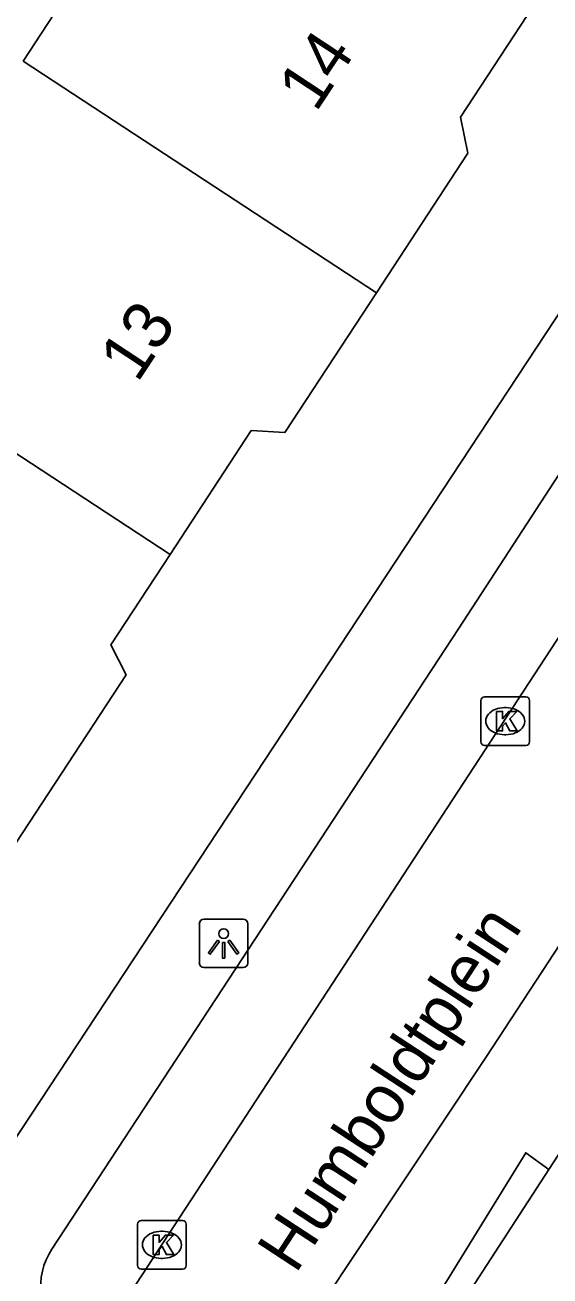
# Model space of a CAD drawing. Extents: x 159280 to 160375, y 384531 to 385872.
# Drawn here: x 160024.02 to 160034.82, y 384678.69 to 384704.43 of the extents above; entities that cross this region are included whole.
import ezdxf

# ---------------------------------------------------------------- set-up
doc = ezdxf.new("R2010")
doc.units = 0
for name, color, linetype in [('IMGEO_Groenvoorziening', 7, 'Continuous'), ('IMGEO_Haag', 7, 'Continuous'), ('IMGEO_Hek', 7, 'Continuous'), ('IMGEO_Kolk', 7, 'Continuous'), ('IMGEO_Lichtpunt', 7, 'Continuous'), ('IMGEO_Openbare_ruimte_label', 7, 'Continuous'), ('IMGEO_Pand', 7, 'Continuous'), ('IMGEO_Pand_nummerreeks', 7, 'Continuous'), ('IMGEO_Rijbaan_lokaal_open', 7, 'Continuous'), ('IMGEO_Voetpad_open', 7, 'Continuous')]:
    doc.layers.add(name, color=color, linetype=linetype)

msp = doc.modelspace()

# ---------------------------------------------------------------- linework, layer by layer
at = {"layer": 'IMGEO_Groenvoorziening'}
msp.add_lwpolyline([(160034.8, 384680.882), (160036.061, 384682.822)], dxfattribs=at)
at = {"layer": 'IMGEO_Haag'}
for points in [[(160048.985, 384693.728), (160048.916, 384693.623), (160048.278, 384692.664), (160051.453, 384690.78), (160040.213, 384673.657), (160033.098, 384678.263), (160034.8, 384680.882)], [(160034.8, 384680.882), (160034.326, 384681.227), (160032.35, 384678.026)]]:
    msp.add_lwpolyline(points, dxfattribs=at)
at = {"layer": 'IMGEO_Hek'}
msp.add_lwpolyline([(160051.453, 384690.78), (160040.213, 384673.657), (160033.098, 384678.263), (160034.8, 384680.882), (160036.061, 384682.822), (160044.27, 384695.449)], dxfattribs=at)
at = {"layer": 'IMGEO_Kolk'}
for p, q in [((160033.479, 384690.608), (160034.331, 384690.608)), ((160033.404, 384689.682), (160033.404, 384690.534)), ((160033.892, 384690.388), (160033.917, 384690.388)), ((160034.405, 384690.534), (160034.405, 384689.682)), ((160033.915, 384689.828), (160033.89, 384689.828)), ((160034.331, 384689.608), (160033.479, 384689.608)), ((160026.339, 384678.907), (160026.339, 384679.759)), ((160026.414, 384679.833), (160027.266, 384679.833)), ((160027.34, 384679.759), (160027.34, 384678.907)), ((160026.827, 384679.613), (160026.852, 384679.613)), ((160026.85, 384679.053), (160026.825, 384679.053)), ((160027.266, 384678.833), (160026.414, 384678.833))]:
    msp.add_line(p, q, dxfattribs=at)
for points in [[(160033.479, 384690.608), (160034.331, 384690.608)], [(160033.404, 384689.682), (160033.404, 384690.534)], [(160033.725, 384690.308), (160033.848, 384690.308), (160033.848, 384690.157), (160033.978, 384690.308), (160034.142, 384690.308), (160033.996, 384690.157), (160034.149, 384689.908), (160033.997, 384689.908), (160033.912, 384690.072), (160033.848, 384690.005), (160033.848, 384689.908), (160033.725, 384689.908), (160033.725, 384690.308)], [(160034.405, 384690.534), (160034.405, 384689.682)], [(160034.331, 384689.608), (160033.479, 384689.608)], [(160026.339, 384678.907), (160026.339, 384679.759)], [(160026.414, 384679.833), (160027.266, 384679.833)], [(160027.34, 384679.759), (160027.34, 384678.907)], [(160026.66, 384679.533), (160026.783, 384679.533), (160026.783, 384679.382), (160026.913, 384679.533), (160027.077, 384679.533), (160026.931, 384679.382), (160027.084, 384679.133), (160026.932, 384679.133), (160026.847, 384679.297), (160026.783, 384679.23), (160026.783, 384679.133), (160026.66, 384679.133), (160026.66, 384679.533)], [(160027.266, 384678.833), (160026.414, 384678.833)]]:
    msp.add_lwpolyline(points, dxfattribs=at)
for centre, start, end in [((160033.481, 384690.532), 91.552, 178.448), ((160033.481, 384690.532), 91.552, 178.448), ((160034.329, 384690.532), 1.552, 88.448), ((160034.329, 384690.532), 1.552, 88.448), ((160033.481, 384689.684), 181.552, 268.448), ((160033.481, 384689.684), 181.552, 268.448), ((160034.329, 384689.684), 271.552, 358.448), ((160034.329, 384689.684), 271.552, 358.448), ((160026.416, 384679.757), 91.552, 178.448), ((160026.416, 384679.757), 91.552, 178.448), ((160027.264, 384679.757), 1.552, 88.448), ((160027.264, 384679.757), 1.552, 88.448), ((160026.416, 384678.909), 181.552, 268.448), ((160026.416, 384678.909), 181.552, 268.448), ((160027.264, 384678.909), 271.552, 358.448), ((160027.264, 384678.909), 271.552, 358.448)]:
    msp.add_arc(centre, 0.0765, start, end, dxfattribs=at)
for centre, major_axis, ratio, start_param, end_param in [((160033.891, 384690.108), (-0.387, 0.002), 0.722429, 4.712389, 7.853982), ((160033.916, 384690.108), (-0.39, 0.002), 0.717154, 1.570796, 4.712389), ((160026.826, 384679.333), (-0.387, 0.002), 0.722429, 4.712389, 7.853982), ((160026.851, 384679.333), (-0.39, 0.002), 0.717154, 1.570796, 4.712389)]:
    msp.add_ellipse(centre, major_axis=major_axis, ratio=ratio, start_param=start_param, end_param=end_param, dxfattribs=at)
at = {"layer": 'IMGEO_Lichtpunt'}
for p, q in [((160027.61, 384685.938), (160027.61, 384685.131)), ((160027.61, 384685.938), (160027.61, 384685.131)), ((160028.512, 384686.033), (160027.704, 384686.033)), ((160028.512, 384686.033), (160027.704, 384686.033)), ((160028.606, 384685.131), (160028.606, 384685.938)), ((160028.606, 384685.131), (160028.606, 384685.938)), ((160027.704, 384685.037), (160028.512, 384685.037)), ((160027.704, 384685.037), (160028.512, 384685.037))]:
    msp.add_line(p, q, dxfattribs=at)
for points in [[(160027.984, 384685.602), (160028.023, 384685.574), (160027.835, 384685.312), (160027.797, 384685.339), (160027.984, 384685.602)], [(160028.086, 384685.554), (160028.133, 384685.554), (160028.133, 384685.232), (160028.086, 384685.232), (160028.086, 384685.554)], [(160028.196, 384685.574), (160028.234, 384685.601), (160028.421, 384685.339), (160028.382, 384685.311), (160028.196, 384685.574)]]:
    msp.add_lwpolyline(points, dxfattribs=at)
msp.add_circle((160028.109, 384685.736), 0.0994, dxfattribs=at)
for centre, start, end in [((160027.704, 384685.938), 90, 180), ((160027.704, 384685.938), 90, 180), ((160028.512, 384685.938), 0, 90), ((160028.512, 384685.938), 0, 90), ((160027.704, 384685.131), 180, 270), ((160027.704, 384685.131), 180, 270), ((160028.512, 384685.131), 270, 0), ((160028.512, 384685.131), 270, 360)]:
    msp.add_arc(centre, 0.0946, start, end, dxfattribs=at)
at = {"layer": 'IMGEO_Pand'}
for points in [[(160023.982, 384703.687), (160026.018, 384706.795), (160025.579, 384707.083), (160026.329, 384708.229), (160019.851, 384712.473), (160020.038, 384712.758)], [(160034.354, 384704.627), (160032.982, 384702.534), (160033.136, 384701.794), (160031.254, 384698.921)], [(160031.254, 384698.921), (160023.982, 384703.687)], [(160015.421, 384701.131), (160020.44, 384697.843), (160027.009, 384693.54)], [(160031.254, 384698.921), (160029.372, 384696.049), (160028.679, 384696.088), (160027.009, 384693.54)], [(160027.009, 384693.54), (160025.791, 384691.68), (160026.102, 384691.061), (160023.834, 384687.599)]]:
    msp.add_lwpolyline(points, dxfattribs=at)
at = {"layer": 'IMGEO_Rijbaan_lokaal_open'}
for points in [[(160041.908, 384702.4), (160024.064, 384675.097)], [(160044.661, 384700.228), (160033.505, 384683.188), (160027.501, 384674.16)]]:
    msp.add_lwpolyline(points, dxfattribs=at)
at = {"layer": 'IMGEO_Voetpad_open'}
for points in [[(160041.163, 384719.572), (160040.444, 384707.372), (160039.931, 384705.971), (160020.662, 384676.735)], [(160024.064, 384675.097), (160024.201, 384675.328), (160024.316, 384675.571), (160024.409, 384675.823), (160024.479, 384676.083), (160024.526, 384676.347), (160024.549, 384676.615), (160024.548, 384676.884), (160024.523, 384677.151), (160024.521, 384677.167), (160024.36, 384678.273), (160024.357, 384678.293), (160024.346, 384678.417), (160024.347, 384678.541), (160024.358, 384678.665), (160024.38, 384678.788), (160024.413, 384678.908), (160024.457, 384679.024), (160024.511, 384679.136), (160024.575, 384679.243), (160032.944, 384692.007), (160039.127, 384701.512), (160039.528, 384701.866), (160040.528, 384702.267)]]:
    msp.add_lwpolyline(points, dxfattribs=at)

# ---------------------------------------------------------------- texts
at = {"layer": 'IMGEO_Openbare_ruimte_label'}
msp.add_text('Humboldtplein', height=1, rotation=56.7865, dxfattribs=at).set_placement((160029.591, 384678.719))
at = {"layer": 'IMGEO_Pand_nummerreeks'}
for s, p in [('14', (160030.009, 384702.618)), ('13', (160026.335, 384697.052))]:
    msp.add_text(s, height=1, rotation=56.576, dxfattribs=at).set_placement(p)

doc.saveas('drawing.dxf')
